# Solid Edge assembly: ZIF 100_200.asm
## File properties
Title: Zylinder
Author: bmolnar
Template: iso metric assembly.asm
Last saved by: psaghy
Revision: 33
Application: Solid Edge
Username: bmolnar
Dokumentum tartalom típus: 1
Document Number: ZIF 100/200
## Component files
Kit_1.par
Profilrohr.par
Kit_2.par
Mutter.par
Kolbenstange.par
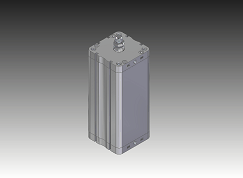
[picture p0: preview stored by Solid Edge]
